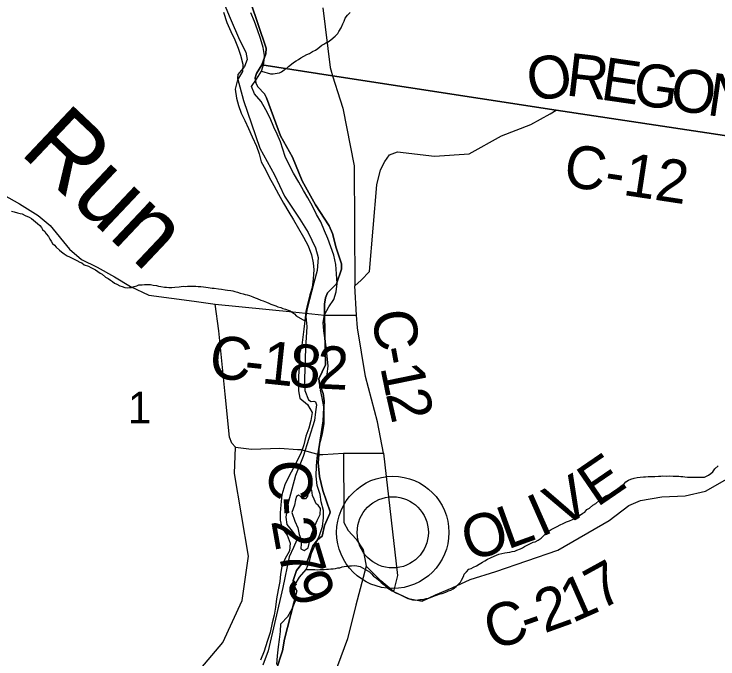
# Model space of a CAD drawing. Extents: x 0.4 to 34.4, y -2.1 to 19.9.
# Drawn here: x 3.589 to 4.522, y 15.936 to 16.79 of the extents above; entities that cross this region are included whole.
import ezdxf

# ---------------------------------------------------------------- set-up
doc = ezdxf.new("R2010")
doc.units = 0
for name, color, linetype in [('GM_X_County_Road', 7, 'Continuous'), ('GM_X_County_Road_Text', 7, 'Continuous'), ('GM_X_County_ROW', 7, 'Continuous'), ('GM_X_Major_River', 7, 'Continuous'), ('GM_X_Minor_River', 7, 'Continuous'), ('GM_X_Minor_River_Text', 7, 'Continuous'), ('GM_X_Section', 7, 'Continuous'), ('GM_X_Section_Text', 7, 'Continuous'), ('GM_X_Township', 7, 'Continuous'), ('GM_X_Township_Road', 7, 'Continuous'), ('GM_X_Unincorporated', 7, 'Continuous')]:
    doc.layers.add(name, color=color, linetype=linetype)

msp = doc.modelspace()

# ---------------------------------------------------------------- linework, layer by layer
at = {"layer": 'GM_X_County_Road'}
for points in [[(3.99822, 16.79852), (4.00787, 16.71946), (4.00885, 16.7163)], [(4.00885, 16.7163), (4.01127, 16.70856), (4.02123, 16.67669), (4.02465, 16.66574), (4.04002, 16.58926), (4.04094, 16.42995)], [(4.29942, 16.65823), (4.30751, 16.6628), (4.58047, 16.62174), (4.65716, 16.61209)], [(4.04094, 16.42995), (4.04916, 16.43784), (4.06037, 16.44902), (4.06979, 16.56381), (4.07473, 16.58383), (4.08064, 16.5951), (4.0865, 16.60372), (4.0972, 16.60769), (4.14641, 16.60183), (4.19238, 16.60515), (4.23534, 16.62901), (4.27394, 16.64384), (4.29942, 16.65823)], [(3.56748, 16.55452), (3.59639, 16.53895), (3.62085, 16.52339), (3.63679, 16.51005), (3.66236, 16.47892), (3.67829, 16.4652), (3.69941, 16.45482), (3.72203, 16.44222), (3.74352, 16.42926), (3.76761, 16.41777), (3.82765, 16.40979), (3.85563, 16.4059)], [(4.07851, 16.2085), (4.07058, 16.25), (4.05504, 16.30987), (4.04414, 16.37457), (4.04284, 16.39121), (4.04094, 16.42995)], [(3.85563, 16.4059), (3.95848, 16.39561)], [(3.95848, 16.39561), (4.00067, 16.39139), (4.04284, 16.39121)], [(4.02592, 16.20823), (4.07851, 16.2085)], [(4.02592, 16.20823), (4.02605, 16.13015), (4.02626, 16.11649), (4.03182, 16.10579), (4.0423, 16.09465), (4.05161, 16.0805), (4.0559, 16.05881)], [(4.07851, 16.2085), (4.09746, 16.04616), (4.09205, 16.02496)], [(4.09205, 16.02496), (4.11198, 16.01586), (4.12976, 16.01249), (4.14774, 16.02088), (4.16955, 16.02996), (4.19366, 16.04089), (4.22764, 16.05164), (4.30976, 16.08008), (4.37804, 16.11902), (4.40385, 16.13903), (4.41915, 16.14558), (4.44771, 16.15073), (4.47846, 16.15168), (4.50552, 16.158), (4.54964, 16.18336), (4.59021, 16.18184), (4.60645, 16.17812), (4.62887, 16.15987), (4.66201, 16.12737), (4.67626, 16.11875), (5.14724, 16.06516)], [(4.09205, 16.02496), (4.075, 16.03922), (4.0559, 16.05881), (4.04199, 16.00697), (4.03083, 15.96231), (4.01787, 15.92679), (3.93916, 15.75501), (3.87521, 15.61077), (3.85713, 15.55897), (3.84447, 15.51546), (3.83285, 15.46473), (3.82253, 15.39538), (3.79803, 14.90777), (3.79273, 14.8467), (3.78744, 14.81678), (3.76829, 14.77068), (3.74159, 14.72734), (3.68302, 14.6568)]]:
    msp.add_lwpolyline(points, dxfattribs=at)
at = {"layer": 'GM_X_County_ROW'}
for points in [[(3.88249, 16.21616), (3.90362, 16.21356), (3.94142, 16.21504), (3.96485, 16.21348)], [(3.96485, 16.21348), (3.96922, 16.21319), (3.99281, 16.20685), (3.99816, 16.20683), (4.02592, 16.20823)]]:
    msp.add_lwpolyline(points, dxfattribs=at)
at = {"layer": 'GM_X_Major_River'}
for points in [[(3.86668, 16.79296), (3.87102, 16.77925), (3.87615, 16.76741), (3.88167, 16.75595), (3.88606, 16.74526), (3.88932, 16.73573), (3.89218, 16.72393), (3.89164, 16.71408), (3.88502, 16.70318), (3.88217, 16.69071), (3.88389, 16.67893), (3.88639, 16.66903), (3.89003, 16.65911), (3.89481, 16.64918), (3.89958, 16.63849), (3.90472, 16.62741), (3.91023, 16.61519), (3.91386, 16.60489), (3.91636, 16.59461), (3.92227, 16.58428), (3.92705, 16.57435), (3.93333, 16.56325), (3.93961, 16.55178), (3.94626, 16.53992), (3.95328, 16.52768), (3.95958, 16.51772), (3.96623, 16.50624), (3.97289, 16.49475), (3.97878, 16.48328), (3.98315, 16.47146), (3.98564, 16.4608), (3.98626, 16.45131), (3.98569, 16.43957), (3.984, 16.42784), (3.98118, 16.41802), (3.97837, 16.40744), (3.97591, 16.3961), (3.97458, 16.38361), (3.97327, 16.37263), (3.97159, 16.36204), (3.97029, 16.35144), (3.96746, 16.34049), (3.9668, 16.32229), (3.96586, 16.31055), (3.96609, 16.30107), (3.96594, 16.29121), (3.96768, 16.28132), (3.9778, 16.27282), (3.98408, 16.2621), (3.9824, 16.25151), (3.97959, 16.24169), (3.97563, 16.23076), (3.97318, 16.21942), (3.9696, 16.20923), (3.96451, 16.19907), (3.95903, 16.18816), (3.95356, 16.17838), (3.94806, 16.16633), (3.94406, 16.15312), (3.94272, 16.13987), (3.94179, 16.12926), (3.94165, 16.11978), (3.94415, 16.1095), (3.95082, 16.09954), (3.95484, 16.08923), (3.95392, 16.07901), (3.94806, 16.0681), (3.94411, 16.0583), (3.94206, 16.04809), (3.94115, 16.03824), (3.93908, 16.02728), (3.937, 16.01517), (3.93569, 16.00419), (3.934, 15.9936), (3.9312, 15.98378), (3.92833, 15.97055), (3.92474, 15.95885), (3.92074, 15.94602), (3.91562, 15.93396)], [(4.00422, 16.33688), (4.0029, 16.34942), (3.99981, 16.3707), (3.99884, 16.38172), (4.00052, 16.39193), (4.00638, 16.40246), (4.01298, 16.41221), (4.01618, 16.4224), (4.0171, 16.43339), (4.01654, 16.44591), (4.0156, 16.45844), (4.01275, 16.471), (4.00913, 16.48205), (4.00512, 16.49274), (4.00072, 16.50304), (3.99559, 16.51488), (3.99005, 16.52483), (3.98453, 16.53553), (3.97825, 16.54663), (3.97271, 16.55657), (3.96643, 16.56767), (3.9594, 16.57953), (3.95276, 16.59215), (3.94836, 16.6017), (3.94547, 16.61123), (3.9422, 16.62114), (3.9378, 16.63107), (3.9334, 16.64061), (3.92864, 16.65245), (3.92275, 16.66353), (3.91646, 16.67463), (3.90789, 16.68463), (3.90386, 16.69417), (3.91047, 16.70393), (3.91709, 16.71482), (3.92028, 16.72501), (3.92083, 16.73562), (3.91909, 16.74588), (3.91586, 16.75807), (3.91186, 16.76951), (3.90786, 16.78057), (3.90272, 16.79202)], [(3.93717, 15.92831), (3.93811, 15.94005), (3.93943, 15.95179), (3.94072, 15.96163), (3.94203, 15.97223), (3.94256, 15.98209), (3.95182, 15.99218), (3.95767, 16.00195), (3.96201, 16.01288), (3.96068, 16.02466), (3.96159, 16.03451), (3.96743, 16.04428), (3.97632, 16.05438), (3.98066, 16.06493), (3.9831, 16.0759), (3.9886, 16.08795), (3.99409, 16.09924), (3.99769, 16.11132), (3.99939, 16.12267), (3.99916, 16.13254), (3.9963, 16.14396), (3.99456, 16.15385), (3.99094, 16.16566), (3.98961, 16.17782), (3.98983, 16.19185), (3.99075, 16.20207), (3.99321, 16.21417), (3.99527, 16.22438), (3.99808, 16.23458), (4.00018, 16.24744), (3.99998, 16.2592), (3.99977, 16.26982), (3.99729, 16.28162), (3.99518, 16.29189), (3.99952, 16.30282), (4.00385, 16.31261), (4.00517, 16.32435), (4.00422, 16.33688)], [(3.98363, 16.15933), (3.97984, 16.15977), (3.97865, 16.15637), (3.97782, 16.15146), (3.97548, 16.1477), (3.97169, 16.14776), (3.96908, 16.15121), (3.96607, 16.15278), (3.96339, 16.15092), (3.96218, 16.14677), (3.96093, 16.13958), (3.95736, 16.12978), (3.96098, 16.11834), (3.96502, 16.10955), (3.96678, 16.10081)], [(3.96678, 16.10081), (3.96897, 16.0947), (3.96964, 16.08862), (3.96914, 16.08143), (3.97367, 16.07946), (3.97865, 16.08279), (3.98027, 16.08884), (3.9811, 16.09375), (3.98351, 16.10206), (3.98704, 16.10997), (3.99098, 16.11901), (3.9949, 16.12729), (3.99502, 16.13488), (3.99206, 16.13947), (3.98943, 16.14141), (3.98687, 16.14752), (3.98466, 16.15211), (3.98363, 16.15933)]]:
    msp.add_lwpolyline(points, dxfattribs=at)
at = {"layer": 'GM_X_Minor_River'}
for points in [[(3.91709, 16.71482), (3.92885, 16.7112), (3.93228, 16.71114), (3.93495, 16.71147), (3.93763, 16.7118), (3.94069, 16.7125), (3.9434, 16.71397), (3.94726, 16.71619), (3.94997, 16.71804), (3.95271, 16.72103), (3.95658, 16.724), (3.9593, 16.72624), (3.96278, 16.72846), (3.96626, 16.73029), (3.96897, 16.73215), (3.97321, 16.73435), (3.97707, 16.73656), (3.98054, 16.73802), (3.98441, 16.74061), (3.98865, 16.74244), (3.99175, 16.74466), (3.9968, 16.74914), (3.9995, 16.75061), (4.00221, 16.75208), (4.00529, 16.75355), (4.00878, 16.75614), (4.01461, 16.76098), (4.01812, 16.76472), (4.01971, 16.76736), (4.02248, 16.77187), (4.02488, 16.77715), (4.0265, 16.78093), (4.02811, 16.7847), (4.03087, 16.78884), (4.03437, 16.7922)], [(3.5858, 16.52917), (3.58921, 16.52835), (3.59376, 16.52712), (3.59716, 16.52592), (3.59982, 16.52549), (3.60359, 16.52352), (3.60888, 16.52114), (3.61226, 16.51918), (3.61489, 16.51722), (3.6175, 16.51489), (3.62012, 16.51256), (3.62312, 16.51023), (3.62534, 16.50752), (3.62681, 16.50483), (3.6298, 16.50211), (3.63164, 16.49904), (3.63461, 16.49556), (3.63643, 16.4921), (3.63828, 16.4894), (3.64012, 16.48633), (3.64273, 16.484), (3.64496, 16.48129), (3.64907, 16.47741), (3.65207, 16.47507), (3.65544, 16.47273), (3.65958, 16.46999), (3.66259, 16.46842), (3.66674, 16.46644), (3.66975, 16.46486), (3.6724, 16.46367), (3.67617, 16.4617), (3.67881, 16.46051), (3.68181, 16.45817), (3.68786, 16.45616), (3.69088, 16.45458), (3.69426, 16.45262), (3.6969, 16.45143), (3.70028, 16.44908), (3.70329, 16.44712), (3.70592, 16.44555), (3.71003, 16.44168), (3.7138, 16.4397), (3.7168, 16.43775), (3.71943, 16.4358), (3.72205, 16.43385), (3.72507, 16.43227), (3.72922, 16.43029), (3.73224, 16.42909), (3.73603, 16.42788), (3.73907, 16.42745), (3.74212, 16.42777), (3.7448, 16.4281), (3.74826, 16.42918), (3.75171, 16.43026), (3.75441, 16.43135), (3.75899, 16.43165), (3.76205, 16.43197), (3.76662, 16.43189), (3.76967, 16.43183), (3.77346, 16.431), (3.77765, 16.43054), (3.78068, 16.42973), (3.78372, 16.42929), (3.78827, 16.42845), (3.79094, 16.4284), (3.79398, 16.42796), (3.79817, 16.42789), (3.80199, 16.4282), (3.80773, 16.42885), (3.8104, 16.42918), (3.81346, 16.42951), (3.81613, 16.42946), (3.8188, 16.42979), (3.82376, 16.4297), (3.82681, 16.42964), (3.82986, 16.42959), (3.8329, 16.42915), (3.83671, 16.42908), (3.84013, 16.42864), (3.84317, 16.4282), (3.84622, 16.42815), (3.84888, 16.42772), (3.85154, 16.42729), (3.85421, 16.42724), (3.85991, 16.42637), (3.86409, 16.42592), (3.86903, 16.42507), (3.87206, 16.42425), (3.87624, 16.42379), (3.8789, 16.42336), (3.88155, 16.42255), (3.88535, 16.42172), (3.88875, 16.42052), (3.89254, 16.41969), (3.89519, 16.4185)], [(3.89519, 16.4185), (3.89823, 16.41806), (3.90126, 16.41725), (3.90542, 16.41565), (3.90844, 16.41445), (3.91146, 16.41325), (3.91599, 16.41127), (3.9194, 16.41007), (3.92356, 16.40847), (3.92658, 16.40727), (3.92922, 16.40608), (3.93225, 16.40488), (3.93603, 16.40367), (3.93867, 16.40248), (3.94246, 16.40127), (3.94548, 16.40008), (3.94889, 16.39925), (3.9523, 16.39805), (3.95494, 16.39686), (3.95795, 16.3949), (3.96057, 16.39295), (3.96318, 16.39024), (3.97458, 16.38361)], [(4.32924, 16.12063), (4.33349, 16.12283), (4.3362, 16.12469), (4.33967, 16.12652), (4.34277, 16.12875), (4.34547, 16.13022), (4.34822, 16.1336), (4.35169, 16.13543), (4.35598, 16.13954), (4.36022, 16.14175), (4.36411, 16.1451), (4.36683, 16.14733), (4.36954, 16.14919), (4.37341, 16.15178), (4.37764, 16.1536), (4.38112, 16.15582), (4.38539, 16.15879), (4.39042, 16.16212), (4.39392, 16.1651), (4.39778, 16.16769), (4.40013, 16.17031), (4.40361, 16.17253), (4.4067, 16.174), (4.41092, 16.17544), (4.41513, 16.17612), (4.41896, 16.17682), (4.42316, 16.17712), (4.42583, 16.17707), (4.42965, 16.17738), (4.43232, 16.17771), (4.43842, 16.1776), (4.44339, 16.17789), (4.44643, 16.17783), (4.44911, 16.17817), (4.45368, 16.17808), (4.45789, 16.17839), (4.46245, 16.17792), (4.46702, 16.17784), (4.47007, 16.17778), (4.47273, 16.17735), (4.4754, 16.1773), (4.47807, 16.17725), (4.48187, 16.1768), (4.48454, 16.17675), (4.48721, 16.17671), (4.49178, 16.17662), (4.49711, 16.17652), (4.50093, 16.17645), (4.50398, 16.17678), (4.50668, 16.17787), (4.50938, 16.17934), (4.51248, 16.18157), (4.5152, 16.1838), (4.51795, 16.18756), (4.52224, 16.19166)], [(3.97632, 16.05438), (3.98766, 16.05422), (3.9907, 16.05378), (3.99414, 16.0541), (3.99718, 16.05404), (4.00024, 16.05437), (4.0033, 16.05469), (4.00597, 16.05464), (4.00903, 16.05497), (4.01208, 16.05529), (4.01514, 16.05562), (4.01821, 16.05632), (4.02088, 16.05665), (4.02396, 16.05774), (4.02663, 16.05807), (4.03084, 16.05875), (4.03352, 16.05908), (4.03619, 16.05903), (4.03963, 16.05935), (4.04343, 16.0589), (4.0476, 16.05807), (4.051, 16.05648), (4.05401, 16.0549), (4.05702, 16.05295), (4.06003, 16.05099), (4.06264, 16.04866), (4.06562, 16.04556), (4.06937, 16.04283), (4.07236, 16.04011), (4.07572, 16.037), (4.07947, 16.03389), (4.0832, 16.0304), (4.08658, 16.02805), (4.09035, 16.02608), (4.096, 16.02293), (4.10053, 16.02095), (4.10393, 16.01936), (4.10731, 16.0174), (4.11109, 16.01581), (4.1145, 16.01499), (4.11715, 16.01418), (4.12057, 16.01373), (4.12401, 16.01405), (4.12707, 16.01437), (4.13127, 16.01468), (4.13511, 16.01575), (4.13894, 16.01644), (4.14432, 16.01863), (4.14893, 16.02006), (4.15393, 16.02187), (4.15661, 16.02259), (4.16123, 16.0244), (4.16507, 16.02585), (4.16777, 16.02695), (4.17124, 16.02878), (4.17512, 16.03176), (4.17824, 16.03474), (4.18058, 16.03736), (4.18217, 16.04), (4.18495, 16.04489), (4.18578, 16.04792), (4.18852, 16.0513), (4.19203, 16.05466), (4.19472, 16.05575), (4.19819, 16.05721), (4.20204, 16.05904), (4.20552, 16.06126), (4.20977, 16.06385), (4.21286, 16.06569), (4.21673, 16.0679), (4.22058, 16.06973), (4.22521, 16.07193), (4.22867, 16.07339), (4.23175, 16.07448), (4.23558, 16.07555), (4.23941, 16.07624), (4.24247, 16.07656), (4.2463, 16.07725), (4.24936, 16.07796), (4.25281, 16.07865), (4.2555, 16.07975), (4.26012, 16.08157), (4.26282, 16.08304), (4.26553, 16.08489), (4.27015, 16.08709), (4.27362, 16.08855), (4.27709, 16.09039), (4.27978, 16.0911), (4.28363, 16.09293), (4.28751, 16.0959), (4.29218, 16.1), (4.2953, 16.10337), (4.2984, 16.10559), (4.30111, 16.10707), (4.30458, 16.10891), (4.30882, 16.11111), (4.31307, 16.11332), (4.31692, 16.11515), (4.32116, 16.11735), (4.32539, 16.1188), (4.32924, 16.12063)]]:
    msp.add_lwpolyline(points, dxfattribs=at)
at = {"layer": 'GM_X_Section'}
msp.add_lwpolyline([(3.86731, 16.80396), (3.87569, 16.78488), (3.88769, 16.75627), (3.89611, 16.73984), (3.89784, 16.72996), (3.89465, 16.72093), (3.88575, 16.7101), (3.88529, 16.70519), (3.89311, 16.67589), (3.90355, 16.64466), (3.91473, 16.61266), (3.9342, 16.57748), (3.94771, 16.54884), (3.96801, 16.51857), (3.97906, 16.50096), (3.98855, 16.48035), (3.99212, 16.46779), (3.99068, 16.45039), (3.98624, 16.43419), (3.97769, 16.40025), (3.97562, 16.38969), (3.9769, 16.37641), (3.97527, 16.34766), (3.97379, 16.30641), (3.97466, 16.29125), (3.97938, 16.27904), (3.98274, 16.27671), (3.98654, 16.27741), (3.9888, 16.27623), (3.98987, 16.27243), (3.98856, 16.26298), (3.98723, 16.25164), (3.97239, 16.20381), (3.96211, 16.17899), (3.95239, 16.14243), (3.94941, 16.12355), (3.95039, 16.11406), (3.95594, 16.10715), (3.96298, 16.09794), (3.96366, 16.09338), (3.95933, 16.08361), (3.9538, 16.07083), (3.94515, 16.03046), (3.92589, 15.94635), (3.91875, 15.92754)], dxfattribs=at)
at = {"layer": 'GM_X_Township'}
for points in [[(3.90254, 16.80651), (3.92303, 16.74525), (3.92281, 16.73761), (3.91726, 16.72293), (4.01127, 16.70856), (4.3075, 16.6628), (4.58047, 16.62175), (5.11172, 16.5403), (5.09926, 16.70693), (5.07116, 17.14968)], [(3.9364, 15.92101), (3.945, 15.94638), (3.94758, 15.96209), (3.9598, 16.01012), (3.96371, 16.02613), (3.95965, 16.03339), (3.9589, 16.03961), (3.9636, 16.05272), (3.96985, 16.06146), (3.97777, 16.06578), (3.98505, 16.08576), (3.99152, 16.09408), (3.9973, 16.09862), (4.00036, 16.11277), (4.00745, 16.12839), (4.00787, 16.13057), (3.99823, 16.15905), (3.99396, 16.17735), (3.99233, 16.19573), (3.99281, 16.20685), (3.99312, 16.21395), (3.99892, 16.25147), (3.99989, 16.27777), (3.99885, 16.28761), (3.99374, 16.30038), (3.99316, 16.30691), (4.00173, 16.32565), (4.00067, 16.39139), (4.00044, 16.40608), (4.00168, 16.41444), (4.00441, 16.42084), (4.01625, 16.43261), (4.02288, 16.45219), (4.02286, 16.45932), (4.01598, 16.48064), (4.01113, 16.49944), (4.0065, 16.50948), (3.98864, 16.53735), (3.97093, 16.56938), (3.95795, 16.60074), (3.94241, 16.62913), (3.92366, 16.67941), (3.92079, 16.68453), (3.91195, 16.69376), (3.90933, 16.69928), (3.90873, 16.70601), (3.91044, 16.71151), (3.91726, 16.72293), (3.92281, 16.73761), (3.92303, 16.74525), (3.90254, 16.80651)], [(4.58047, 16.62175), (4.3075, 16.6628), (4.01127, 16.70856), (3.91726, 16.72293), (3.91044, 16.71151), (3.90873, 16.70601), (3.90933, 16.69928), (3.91195, 16.69376), (3.92079, 16.68453), (3.92366, 16.67941), (3.94241, 16.62913), (3.95795, 16.60074), (3.97093, 16.56938), (3.98864, 16.53735), (4.0065, 16.50948), (4.01113, 16.49944), (4.01598, 16.48064), (4.02286, 16.45932), (4.02288, 16.45219), (4.01625, 16.43261), (4.00441, 16.42084), (4.00168, 16.41444), (4.00044, 16.40608), (4.00067, 16.39139), (4.00173, 16.32565), (3.99316, 16.30691), (3.99374, 16.30038), (3.99885, 16.28761), (3.99989, 16.27777), (3.99892, 16.25147), (3.99312, 16.21395), (3.99281, 16.20685), (3.99233, 16.19573), (3.99396, 16.17735), (3.99823, 16.15905), (4.00787, 16.13057), (4.00745, 16.12839), (4.00036, 16.11277), (3.9973, 16.09862), (3.99152, 16.09408), (3.98505, 16.08576), (3.97777, 16.06578), (3.96985, 16.06146), (3.9636, 16.05272), (3.9589, 16.03961), (3.95965, 16.03339), (3.96371, 16.02613), (3.9598, 16.01012), (3.94758, 15.96209), (3.945, 15.94638), (3.9364, 15.92101)]]:
    msp.add_lwpolyline(points, dxfattribs=at)
at = {"layer": 'GM_X_Township_Road'}
for points in [[(3.88249, 16.21616), (3.87787, 16.22153), (3.87453, 16.22968), (3.86878, 16.28676), (3.86044, 16.37032), (3.85563, 16.4059)], [(3.28786, 15.57186), (3.30028, 15.82517), (3.45815, 15.81145), (3.58304, 15.79441), (3.60889, 15.79244), (3.67639, 15.82237), (3.71406, 15.86367), (3.74004, 15.8793), (3.77789, 15.87276), (3.79004, 15.87414), (3.79511, 15.88584), (3.82691, 15.91165), (3.86578, 15.95749), (3.89149, 16.01298), (3.89979, 16.07172), (3.88141, 16.18164), (3.88249, 16.21616)]]:
    msp.add_lwpolyline(points, dxfattribs=at)
at = {"layer": 'GM_X_Unincorporated'}
for radius in [0.0744, 0.04716]:
    msp.add_circle((4.09101, 16.10346), radius, dxfattribs=at)

# ---------------------------------------------------------------- texts
at = {"layer": 'GM_X_County_Road_Text'}
for s, height, rotation, p in [('O', 0.05682, 11.01774, (4.2747, 16.67326)), ('R', 0.05682, 353.32664, (4.31917, 16.68264)), ('E', 0.05682, 351.74323, (4.36511, 16.67727)), ('G', 0.05682, 351.74266, (4.40717, 16.67117)), ('O', 0.05682, 351.73853, (4.45665, 16.66398)), ('N', 0.05682, 351.74338, (4.50613, 16.6568)), ('C-12', 0.056818, 351.38498, (4.31543, 16.56285)), ('C', 0.05682, 277.45522, (4.06332, 16.39551)), ('C', 0.05682, 353.73869, (3.84611, 16.309)), ('1', 0.05682, 354.01379, (3.916, 16.30135)), ('8', 0.05682, 354.68836, (3.95153, 16.29763)), ('2', 0.05682, 357.37579, (3.98929, 16.29419)), ('-', 0.05682, 280.4947, (4.06985, 16.34634)), ('-', 0.05682, 353.80206, (3.89257, 16.3039)), ('1', 0.05682, 281.58781, (4.07429, 16.32244)), ('2', 0.05682, 282.92346, (4.08157, 16.28701)), ('E', 0.05682, 34.40298, (4.36176, 16.136)), ('C', 0.05682, 270, (3.92734, 16.1997)), ('V', 0.05682, 29.34809, (4.31353, 16.10861)), ('I', 0.05682, 23.89681, (4.28692, 16.09651)), ('-', 0.05682, 273.38049, (3.92744, 16.14937)), ('O', 0.05682, 17.51679, (4.19281, 16.06458)), ('L', 0.05682, 19.86951, (4.2429, 16.08044)), ('2', 0.05682, 280.14149, (3.92968, 16.11882)), ('7', 0.05682, 286.90248, (3.93756, 16.07725)), ('7', 0.05682, 28.75465, (4.36581, 15.9994)), ('9', 0.05682, 290.28297, (3.9489, 16.04029)), ('1', 0.05682, 23.81223, (4.32899, 15.9829)), ('2', 0.05682, 19.80176, (4.29203, 15.96943)), ('C', 0.05682, 16.8327, (4.22229, 15.94719)), ('-', 0.05682, 19.3069, (4.2695, 15.96154))]:
    msp.add_text(s, height=height, rotation=rotation, dxfattribs=at).set_placement(p)
at = {"layer": 'GM_X_Minor_River_Text'}
msp.add_text('Run', height=0.094696, rotation=316.63013, dxfattribs=at).set_placement((3.59508, 16.60657))
at = {"layer": 'GM_X_Section_Text'}
msp.add_text('1', height=0.04186, rotation=0.00001, dxfattribs=at).set_placement((3.73981, 16.24802))

doc.saveas('drawing.dxf')
